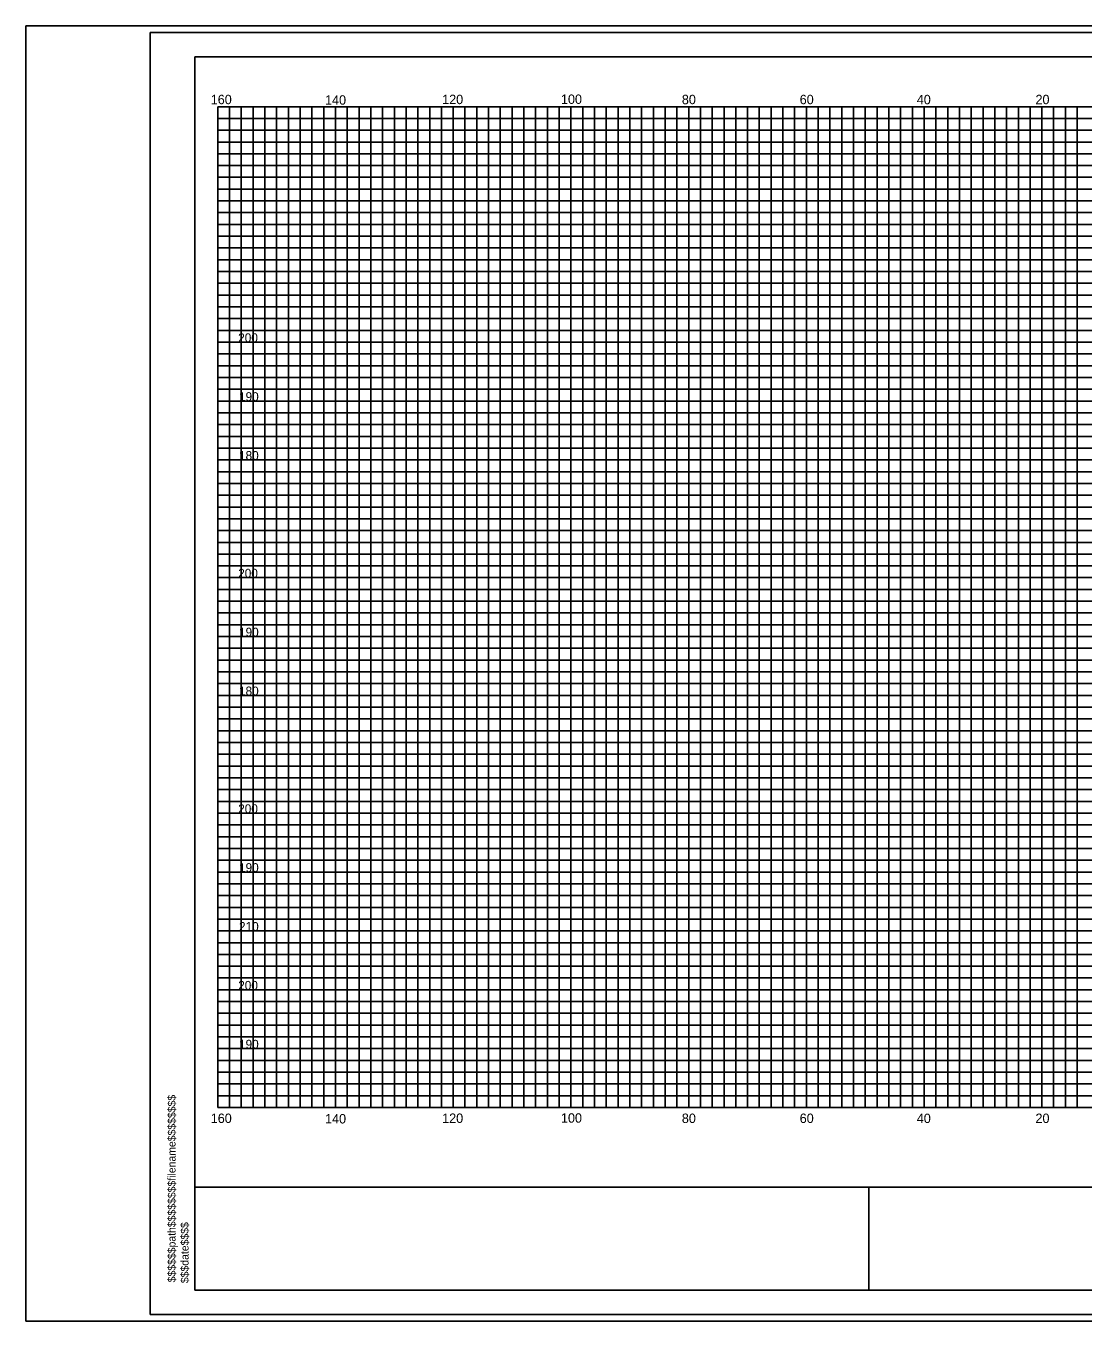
# Model space of a CAD drawing. Extents: x 967 to 1326, y 964 to 3144.
# Drawn here: x 967.4 to 1147, y 963.7 to 1183.7 of the extents above; entities that cross this region are included whole.
import ezdxf

# ---------------------------------------------------------------- set-up
doc = ezdxf.new("R2010")
doc.units = 0
for name, color, linetype in [('Default', 7, 'Continuous'), ('RD_SHT_Bndy', 7, 'Continuous'), ('RD_SHT_IplotShp', 7, 'Continuous'), ('RD_SHT_MjGrid', 7, 'Continuous'), ('RD_SHT_MnGrid', 7, 'Continuous'), ('RD_SHT_TX', 7, 'Continuous'), ('RD_Sketch1', 7, 'Continuous')]:
    doc.layers.add(name, color=color, linetype=linetype)

msp = doc.modelspace()

# ---------------------------------------------------------------- linework, layer by layer
at = {"layer": 'RD_SHT_Bndy'}
for p, q in [((996.11, 968.98), (996.11, 1178.46)), ((996.11, 1178.46), (1323.89, 1178.46)), ((996.11, 986.49), (1323.89, 986.49)), ((1110.59, 968.98), (1110.59, 986.56)), ((1323.89, 968.98), (996.11, 968.98))]:
    msp.add_line(p, q, dxfattribs=at)
at = {"layer": 'RD_SHT_IplotShp'}
for points in [[(967.41, 963.72), (1326.28, 963.72), (1326.28, 1183.72), (967.41, 1183.72)], [(988.52, 964.84), (1326.28, 964.84), (1326.28, 1182.6), (988.52, 1182.6)]]:
    msp.add_lwpolyline(points, close=True, dxfattribs=at)
at = {"layer": 'RD_SHT_MjGrid'}
for p, q in [((1000, 1170), (1320, 1170)), ((1000, 1000), (1000, 1170)), ((1010, 1000), (1010, 1170)), ((1020, 1000), (1020, 1170)), ((1030, 1000), (1030, 1170)), ((1040, 1000), (1040, 1170)), ((1050, 1000), (1050, 1170)), ((1060, 1000), (1060, 1170)), ((1070, 1000), (1070, 1170)), ((1080, 1000), (1080, 1170)), ((1090, 1000), (1090, 1170)), ((1100, 1000), (1100, 1170)), ((1110, 1000), (1110, 1170)), ((1120, 1000), (1120, 1170)), ((1130, 1000), (1130, 1170)), ((1140, 1000), (1140, 1170)), ((1000, 1160), (1320, 1160)), ((1000, 1150), (1320, 1150)), ((1000, 1140), (1320, 1140)), ((1000, 1130), (1320, 1130)), ((1000, 1120), (1320, 1120)), ((1000, 1110), (1320, 1110)), ((1000, 1100), (1320, 1100)), ((1000, 1090), (1320, 1090)), ((1000, 1080), (1320, 1080)), ((1000, 1070), (1320, 1070)), ((1000, 1060), (1320, 1060)), ((1000, 1050), (1320, 1050)), ((1000, 1040), (1320, 1040)), ((1000, 1030), (1320, 1030)), ((1000, 1020), (1320, 1020)), ((1000, 1010), (1320, 1010)), ((1000, 1000), (1320, 1000))]:
    msp.add_line(p, q, dxfattribs=at)
at = {"layer": 'RD_SHT_MnGrid'}
for p, q in [((1002, 1000), (1002, 1170)), ((1004, 1000), (1004, 1170)), ((1006, 1000), (1006, 1170)), ((1008, 1000), (1008, 1170)), ((1012, 1000), (1012, 1170)), ((1014, 1000), (1014, 1170)), ((1016, 1000), (1016, 1170)), ((1018, 1000), (1018, 1170)), ((1022, 1000), (1022, 1170)), ((1024, 1000), (1024, 1170)), ((1026, 1000), (1026, 1170)), ((1028, 1000), (1028, 1170)), ((1032, 1000), (1032, 1170)), ((1034, 1000), (1034, 1170)), ((1036, 1000), (1036, 1170)), ((1038, 1000), (1038, 1170)), ((1042, 1000), (1042, 1170)), ((1044, 1000), (1044, 1170)), ((1046, 1000), (1046, 1170)), ((1048, 1000), (1048, 1170)), ((1052, 1000), (1052, 1170)), ((1054, 1000), (1054, 1170)), ((1056, 1000), (1056, 1170)), ((1058, 1000), (1058, 1170)), ((1062, 1000), (1062, 1170)), ((1064, 1000), (1064, 1170)), ((1066, 1000), (1066, 1170)), ((1068, 1000), (1068, 1170)), ((1072, 1000), (1072, 1170)), ((1074, 1000), (1074, 1170)), ((1076, 1000), (1076, 1170)), ((1078, 1000), (1078, 1170)), ((1082, 1000), (1082, 1170)), ((1084, 1000), (1084, 1170)), ((1086, 1000), (1086, 1170)), ((1088, 1000), (1088, 1170)), ((1092, 1000), (1092, 1170)), ((1094, 1000), (1094, 1170)), ((1096, 1000), (1096, 1170)), ((1098, 1000), (1098, 1170)), ((1102, 1000), (1102, 1170)), ((1104, 1000), (1104, 1170)), ((1106, 1000), (1106, 1170)), ((1108, 1000), (1108, 1170)), ((1112, 1000), (1112, 1170)), ((1114, 1000), (1114, 1170)), ((1116, 1000), (1116, 1170)), ((1118, 1000), (1118, 1170)), ((1122, 1000), (1122, 1170)), ((1124, 1000), (1124, 1170)), ((1126, 1000), (1126, 1170)), ((1128, 1000), (1128, 1170)), ((1132, 1000), (1132, 1170)), ((1134, 1000), (1134, 1170)), ((1136, 1000), (1136, 1170)), ((1138, 1000), (1138, 1170)), ((1142, 1000), (1142, 1170)), ((1144, 1000), (1144, 1170)), ((1146, 1000), (1146, 1170)), ((1000, 1168), (1320, 1168)), ((1000, 1166), (1320, 1166)), ((1000, 1164), (1320, 1164)), ((1000, 1162), (1320, 1162)), ((1000, 1158), (1320, 1158)), ((1000, 1156), (1320, 1156)), ((1000, 1154), (1320, 1154)), ((1000, 1152), (1320, 1152)), ((1000, 1148), (1320, 1148)), ((1000, 1146), (1320, 1146)), ((1000, 1144), (1320, 1144)), ((1000, 1142), (1320, 1142)), ((1000, 1138), (1320, 1138)), ((1000, 1136), (1320, 1136)), ((1000, 1134), (1320, 1134)), ((1000, 1132), (1320, 1132)), ((1000, 1128), (1320, 1128)), ((1000, 1126), (1320, 1126)), ((1000, 1124), (1320, 1124)), ((1000, 1122), (1320, 1122)), ((1000, 1118), (1320, 1118)), ((1000, 1116), (1320, 1116)), ((1000, 1114), (1320, 1114)), ((1000, 1112), (1320, 1112)), ((1000, 1108), (1320, 1108)), ((1000, 1106), (1320, 1106)), ((1000, 1104), (1320, 1104)), ((1000, 1102), (1320, 1102)), ((1000, 1098), (1320, 1098)), ((1000, 1096), (1320, 1096)), ((1000, 1094), (1320, 1094)), ((1000, 1092), (1320, 1092)), ((1000, 1088), (1320, 1088)), ((1000, 1086), (1320, 1086)), ((1000, 1084), (1320, 1084)), ((1000, 1082), (1320, 1082)), ((1000, 1078), (1320, 1078)), ((1000, 1076), (1320, 1076)), ((1000, 1074), (1320, 1074)), ((1000, 1072), (1320, 1072)), ((1000, 1068), (1320, 1068)), ((1000, 1066), (1320, 1066)), ((1000, 1064), (1320, 1064)), ((1000, 1062), (1320, 1062)), ((1000, 1058), (1320, 1058)), ((1000, 1056), (1320, 1056)), ((1000, 1054), (1320, 1054)), ((1000, 1052), (1320, 1052)), ((1000, 1048), (1320, 1048)), ((1000, 1046), (1320, 1046)), ((1000, 1044), (1320, 1044)), ((1000, 1042), (1320, 1042)), ((1000, 1038), (1320, 1038)), ((1000, 1036), (1320, 1036)), ((1000, 1034), (1320, 1034)), ((1000, 1032), (1320, 1032)), ((1000, 1028), (1320, 1028)), ((1000, 1026), (1320, 1026)), ((1000, 1024), (1320, 1024)), ((1000, 1022), (1320, 1022)), ((1000, 1018), (1320, 1018)), ((1000, 1016), (1320, 1016)), ((1000, 1014), (1320, 1014)), ((1000, 1012), (1320, 1012)), ((1000, 1008), (1320, 1008)), ((1000, 1006), (1320, 1006)), ((1000, 1004), (1320, 1004)), ((1000, 1002), (1320, 1002))]:
    msp.add_line(p, q, dxfattribs=at)
at = {"layer": 'RD_Sketch1'}
msp.add_lwpolyline([(967.41, 963.72), (1326.28, 963.72), (1326.28, 1183.72), (967.41, 1183.72)], close=True, dxfattribs=at)

# ---------------------------------------------------------------- texts
at = {"layer": 'Default'}
for s, p in [('200', (1003.47, 1130)), ('190', (1003.61, 1120)), ('180', (1003.61, 1110)), ('200', (1003.47, 1090)), ('190', (1003.61, 1080)), ('180', (1003.61, 1070)), ('200', (1003.47, 1050)), ('190', (1003.61, 1040)), ('210', (1003.61, 1030)), ('200', (1003.47, 1020)), ('190', (1003.61, 1010))]:
    msp.add_text(s, height=1.5, dxfattribs=at).set_placement(p)
for s, p in [('$$$$$$path$$$$$$$$filename$$$$$$$$', (992.83, 970.31)), ('$$$date$$$$', (995.04, 970.17))]:
    msp.add_text(s, height=1.3258, rotation=90, dxfattribs=at).set_placement(p)
at = {"layer": 'RD_SHT_TX'}
for s, p in [('160', (998.81, 1170.42)), ('140', (1018.23, 1170.34)), ('120', (1038.12, 1170.43)), ('100', (1058.3, 1170.47)), ('80', (1078.84, 1170.42)), ('60', (1098.86, 1170.42)), ('40', (1118.75, 1170.41)), ('20', (1138.91, 1170.42)), ('160', (998.81, 997.37)), ('140', (1018.23, 997.29)), ('120', (1038.12, 997.38)), ('100', (1058.3, 997.42)), ('80', (1078.84, 997.37)), ('60', (1098.86, 997.37)), ('40', (1118.75, 997.36)), ('20', (1138.91, 997.37))]:
    msp.add_text(s, height=1.6, dxfattribs=at).set_placement(p)

doc.saveas('drawing.dxf')
